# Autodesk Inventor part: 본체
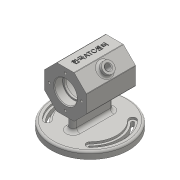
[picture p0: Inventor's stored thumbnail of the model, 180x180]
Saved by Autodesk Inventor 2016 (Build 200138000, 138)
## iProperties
Created: 2017-06
Part Number: 본체
Material: Generic
Document SubType Name: Modeling
Designer: KSEW
Density: 1 g/cm^3
Appearance: Default
Author: KSEW
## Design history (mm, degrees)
sketch "스케치1"
  geometry: L1 (30, -12.426)-(12.426, -30); L2 (12.426, -30)-(-12.426, -30); L3 (-12.426, -30)-(-30, -12.426); L4 (-30, -12.426)-(-30, 12.426); L5 (-30, 12.426)-(-12.426, 30); L6 (-12.426, 30)-(12.426, 30); L7 (12.426, 30)-(30, 12.426); L8 (30, 12.426)-(30, -12.426); C1 r 30 at (0, 0); 3 further points
  constraints: 16 end point, 2 coincident, 1 centre point, 1 midpoint, 1 vertical alignment, 17 other
  dimensions: "d0" = 60 diameter of C1; "d1" = 30 distance from line of point (0, 0) L4
extrude "돌출1" new body sketch "스케치1" stored distance "d2" = 70; taper "d3" = 0 deg
sketch "스케치2"
  geometry: 2 further points
  constraints: 1 vertical alignment
  dimensions: "d4" = 23 distance of point (0, 0) point (0, 23)
hole "구멍1" sketch "스케치2" at (0, 23) diameter "d5" = 3.459; stored, may be unused: countersink angle "d9" = 90 deg, drill point angle "d11" = 118 deg; dims "d6" = 8, "d7" = 4, "d8" = 2, "d10" = 10
sketch "스케치3"
  geometry: L1 (0, 0)-(0, 30); L2 (-26.163, 26.163)-(0, 0); L3 (-26.163, 26.163)-(-20.506, 31.82); L4 (-12.426, 30)-(-30, 12.426) reference; L5 (-26.163, 26.163)-(-20.506, 31.82); L6 (-20.506, 31.82)-(-15.556, 26.87); L7 (-15.556, 26.87)-(-21.213, 21.213); L8 (-21.213, 21.213)-(-26.163, 26.163)
  constraints: 14 end point, 3 parallel, 1 collinear, 1 perpendicular, 1 vertical
  dimensions: "d12" = 45 deg angle of L1 L2; "d13" = 8 distance of L2.start L3.end; "d14" = 7 distance from line of L2.start L4; "d15" = 30 distance of L1.start L1.end; "d16" = 7 distance of L3.end L6.end (= d14)
revolve "회전1" sketch "스케치3" stored, may be unused: angle "d17" = 90 deg
node "작업 평면1"
sketch "스케치4"
  geometry: C1 r 55 at (0, 0); 1 further point
  constraints: 1 centre point, 1 coincident
  dimensions: "d19" = 110 diameter of C1
extrude "돌출2" join sketch "스케치4" distance "d20" = 10; taper "d21" = 0 deg
sketch "스케치5"
  geometry: L1 (0, -24)-(0, 24); L2 (5, -24)-(5, 24); L3 (-5, 24)-(-5, -24); C1 r 55 at (0, 0) reference; A1 r 5 centre (0, -24) between (-5, -24) and (5, -24); A2 r 5 centre (0, 24) between (5, 24) and (-5, 24); 1 further point
  constraints: 8 end point, 4 point on circle, 4 tangent, 2 centre point, 1 coincident, 1 midpoint, 1 parallel, 1 vertical
  dimensions: "d22" = 5 radius of A1; "d23" = 48 distance of L1.end L1.start
extrude "돌출3" join sketch "스케치5" stored distance "d24" = 10; taper "d25" = 0 deg
sketch "스케치6"
  geometry: L1 (-30.406, 30.406)-(0, 0); L2 (-30.406, -30.406)-(0, 0); L3 (-43, 0)-(0, 0); C1 r 55 at (0, 0) reference; A1 r 43 centre (0, 0) between (-30.406, 30.406) and (-30.406, -30.406); A2 r 43 centre (0, 0) between (-30.406, 30.406) and (-30.406, -30.406); A3 r 48 centre (0, 0) between (-33.941, 33.941) and (-33.941, -33.941); A4 r 38 centre (0, 0) between (-26.87, 26.87) and (-26.87, -26.87); A5 r 5 centre (-30.406, 30.406) between (-26.87, 26.87) and (-33.941, 33.941); A6 r 5 centre (-30.406, -30.406) between (-33.941, -33.941) and (-26.87, -26.87)
  constraints: 14 point on circle, 6 centre point, 6 end point, 4 tangent, 2 coincident, 1 horizontal
  dimensions: "d28" = 86 diameter of A1; "d31" = 45 deg angle of L3 L2; "d32" = 90 deg angle of L1 L2; "d33" = 48 radius of A3
extrude "돌출4" cut sketch "스케치6" distance "d34" = 3; taper "d35" = 0 deg
sketch "스케치7"
  geometry: A1 r 48 centre (0, 0) between (-33.941, 33.941) and (-33.941, -33.941) reference; A2 r 5 centre (-30.406, -30.406) between (-33.941, -33.941) and (-26.87, -26.87) reference; A3 r 38 centre (0, 0) between (-26.87, 26.87) and (-26.87, -26.87) reference; A4 r 5 centre (-30.406, 30.406) between (-26.87, 26.87) and (-33.941, 33.941) reference; A5 r 45 centre (0, 0) between (-31.82, 31.82) and (-31.82, -31.82); A6 r 2 centre (-30.406, 30.406) between (-28.991, 28.991) and (-31.82, 31.82); A7 r 41 centre (0, 0) between (-28.991, 28.991) and (-28.991, -28.991); A8 r 2 centre (-30.406, -30.406) between (-31.82, -31.82) and (-28.991, -28.991)
  constraints: 8 point on circle, 4 centre point, 3 other
  dimensions: "d36" = 2 radius of A6
extrude "돌출5" cut sketch "스케치7" stored distance "d37" = 3; taper "d38" = 0 deg
sketch "스케치8"
  geometry: L1 (-35, 16)-(-23, 16); L2 (-23, 16)-(-23, 0); L3 (-23, 0)-(-35, 0); L4 (-35, 0)-(-35, 16); L5 (23, 16)-(35, 16); L6 (35, 16)-(35, 0); L7 (35, 0)-(23, 0); L8 (23, 0)-(23, 16); L9 (-17, 25)-(17, 25); L10 (20, 22)-(20, 0); L11 (20, 0)-(-20, 0); L12 (-20, 0)-(-20, 22); L13 (-35, -12.426)-(-35, 12.426) reference; L14 (35, 12.426)-(35, -12.426) reference; A1 r 3 centre (-17, 22) between (-17, 25) and (-20, 22); A2 r 3 centre (17, 22) between (20, 22) and (17, 25); 4 further points
  constraints: 24 end point, 6 parallel, 5 point on line, 4 point on circle, 4 tangent, 3 horizontal, 3 perpendicular, 2 centre point, 2 horizontal alignment, 1 coincident, 1 equal radius, 1 midpoint
  dimensions: "d39" = 12 distance of L1.start L1.end; "d40" = 12 distance of L5.start L5.end; "d41" = 40 distance of point (-20, 25) point (20, 25); "d42" = 16 distance of L3.end L1.start; "d43" = 16 distance of L5.end L6.end; "d44" = 25 distance of point (20, 25) L10.end; "d45" = 0 distance between parallel lines of L4 L13; "d46" = 0 distance between parallel lines of L14 L6; "d47" = 3 radius of A1
revolve "회전2" sketch "스케치8" stored, may be unused: angle "d48" = 90 deg
sketch "스케치9"
  geometry: C1 r 14 at (0, 0); 1 further point
  constraints: 1 centre point, 1 coincident
  dimensions: "d49" = 28 diameter of C1
extrude "돌출6" cut sketch "스케치9" stored distance "d50" = 70; taper "d51" = 0 deg
fillet "모깎기1" dims "d52" = 0.3
chamfer "모따기1" distance "d53" = 1; stored, may be unused: second distance "d54" = 2, angle "d55" = 45 deg
chamfer "모따기2" distance "d56" = 1; stored, may be unused: second distance "d57" = 2, angle "d58" = 45 deg
sketch "스케치10"
  geometry: C1 r 8 at (0, 0) reference; 1 further point
  constraints: 1 coincident
hole "구멍2" sketch "스케치10" at (0, 0) diameter "d62" = 8; stored, may be unused: countersink angle "d66" = 90 deg, drill point angle "d68" = 118 deg; dims "d63" = 8, "d64" = 4, "d65" = 2, "d67" = 30
chamfer "모따기3" distance "d69" = 1; stored, may be unused: second distance "d70" = 2, angle "d71" = 45 deg
sketch "스케치11"
  geometry: L1 (24.853, -70)-(0, -70) reference; L2 (-17.574, 0)-(-17.574, -70) reference; 2 further points
  constraints: 1 other
  dimensions: "d72" = 35 distance from line of point (12.426, -35) L1; "d73" = 30 distance from line of point (12.426, -35) L2
feature "엠보싱1" sketch "스케치11" dims "d74" = 0.5, "d75" = 0
fillet "모깎기2" dims "d76" = 3
fillet "모깎기3" dims "d77" = 5
fillet "모깎기4" dims "d78" = 3
fillet "모깎기5" dims "d79" = 1
node "솔리드1"
mirror "대칭1"
pattern_circular "원형 패턴1" dims angle "d60" = 360 deg
mirror "대칭2"
other parameters: "d18" = -62, "d29" = 45 deg, "d30" = 45 deg
